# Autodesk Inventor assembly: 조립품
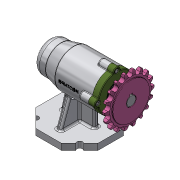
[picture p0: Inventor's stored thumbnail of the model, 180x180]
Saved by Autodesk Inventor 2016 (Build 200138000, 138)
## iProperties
Created: 2021-01
Part Number: 조립품
Material: 일반
Document SubType Name: Assembly
Designer: Administrator
Author: Administrator
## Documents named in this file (12)
- C:\Users\Administrator\Desktop\710106V1032\조립품.iam
- C:\Users\Administrator\Desktop\710106V1032\본체.ipt
- C:\Users\Administrator\Desktop\710106V1032\베어링 6004.ipt
- C:\Users\Administrator\Desktop\710106V1032\베어링 51202.ipt
- C:\Users\Administrator\Desktop\710106V1032\어댑터슬리브.ipt
- C:\Users\Administrator\Desktop\710106V1032\축.ipt
- C:\Users\Administrator\Desktop\710106V1032\볼트 M4.ipt
- C:\Users\Administrator\Desktop\710106V1032\오일 실.ipt
- C:\Users\Administrator\Desktop\710106V1032\커버.ipt
- C:\Users\Administrator\Desktop\710106V1032\멈춤나사 M3.ipt
- C:\Users\Administrator\Desktop\710106V1032\스프로킷.ipt
- C:\Users\Administrator\Desktop\710106V1032\키 5 x 5 x 14.ipt
